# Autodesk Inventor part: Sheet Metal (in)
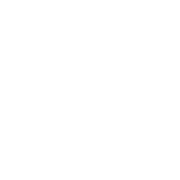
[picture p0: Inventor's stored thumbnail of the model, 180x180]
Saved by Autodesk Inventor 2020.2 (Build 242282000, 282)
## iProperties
Shininess: 64.0
Length Units: 11272
Angle Units: 11279
Time Units: 11290
Mass Units: 11286
Length Display Precision: 3
Angle Display Precision: 2
Compacted: True
Manager: www.cadconsulting.pl
Company: Fabian Stasiak CAD Consulting
Part Number: Sheet Metal (in)
Document SubType Name: Sheet Metal
Created: 2002-07
Material: Generic
Density: 1 g/cm^3
Sheet Metal Rule: Domyślny
Appearance: Default
Designer: F.Stasiak
Density: 0.0
Volumn: 0.0
Area: 0.0
PropertySet Name: Model Information
Control State: 0
Master: False
Checked Out: False
Subject: Zbiór ćwiczeń. Autodesk Inventor 2020. Kurs podstawowy
Author: F.Stasiak
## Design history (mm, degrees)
other parameters: "Thickness" = 3.048, "BendRadius" = 3.048 (= Thickness), "BendReliefWidth" = 3.048 (= Thickness), "BendReliefDepth" = 1.524 (= 0.5 x Thickness), "CornerReliefSize" = 12.192 (= 4 x Thickness), "SeamGap" = 0.00508, "MinimumRemnant" = 6.096 (= 2 x Thickness), "TransitionRadius" = 3.048 (= BendRadius), "JacobiRadiusSize" = 3.048 (= BendRadius), "GapSize" = 3.048 (= Thickness)
